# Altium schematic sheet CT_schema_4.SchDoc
size 284 x 147 mm
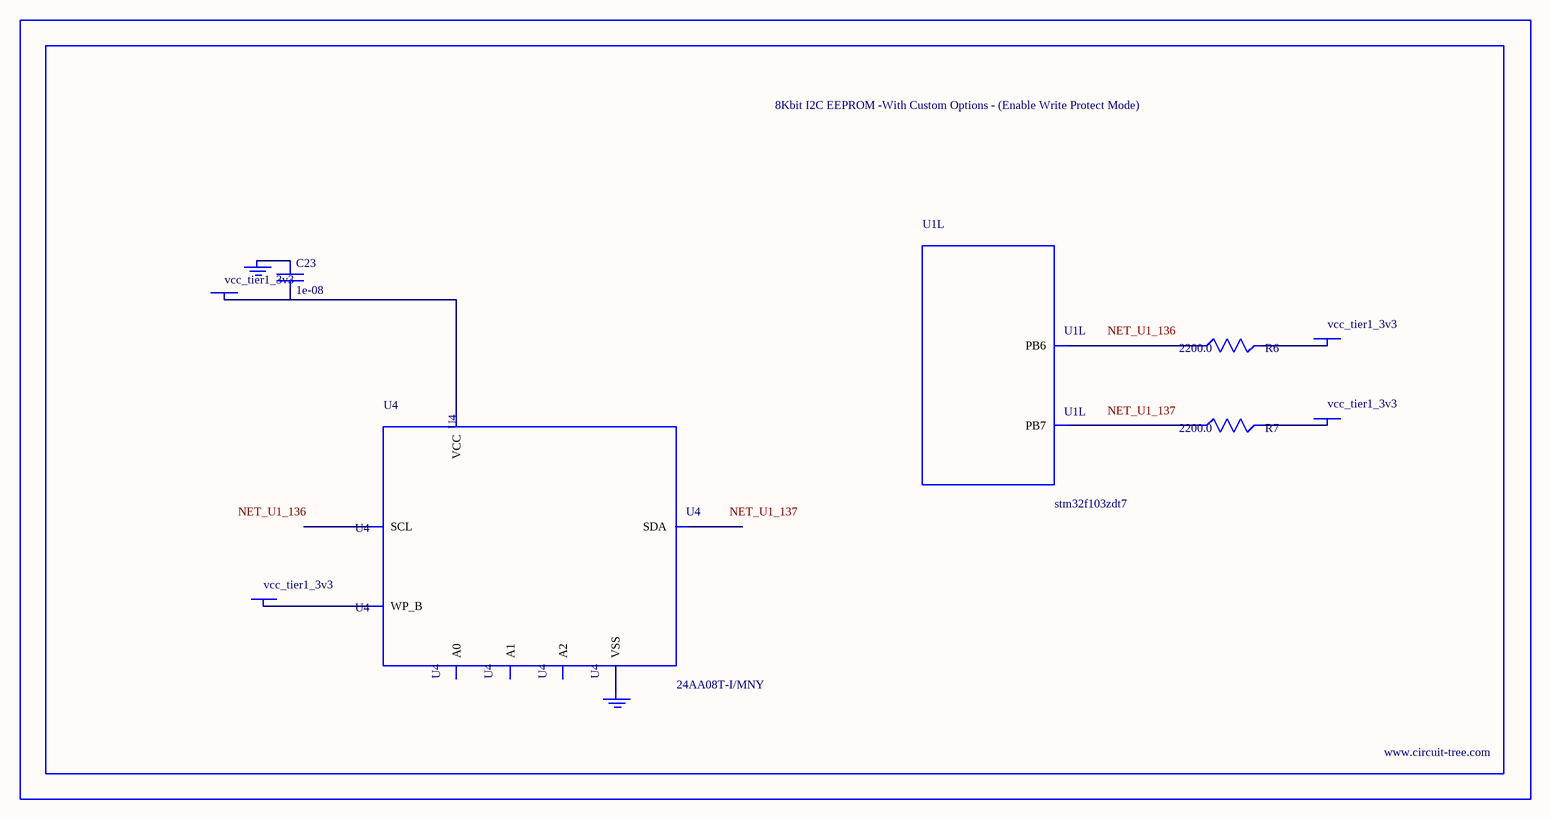
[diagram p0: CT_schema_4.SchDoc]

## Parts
BORDER3  (no value)
C23  1e-08  [C0402]
GND_INSTANCE_3_0  (no value)
GND_INSTANCE_3_1  (no value)
POWER_INSTANCE_3_0  vcc_tier1_3v3
POWER_INSTANCE_3_1  vcc_tier1_3v3
POWER_INSTANCE_3_2  vcc_tier1_3v3
POWER_INSTANCE_3_3  vcc_tier1_3v3
R6  2200.0  [R0603]
R7  2200.0  [R0603]
U1  stm32f103zdt7  [LQFP144]  (part L of 13)
U4  24AA08T-I/MNY  [TDFN-8/6MM]

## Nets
NetC23_1: C23.1 GND_INSTANCE_3_0.0(GND)
NetC23_2: C23.2 POWER_INSTANCE_3_1.0(PWR) U4.8(VCC)
NetGND_INSTANCE_3_1_0: GND_INSTANCE_3_1.0(GND) U4.4(VSS)
NetPOWER_INSTANCE_3_0_0: POWER_INSTANCE_3_0.0(PWR) U4.7(WP_B)
NetPOWER_INSTANCE_3_2_0: POWER_INSTANCE_3_2.0(PWR) R6.2
NetPOWER_INSTANCE_3_3_0: POWER_INSTANCE_3_3.0(PWR) R7.2
NetR6_1: R6.1 U1.136(PB6)
NetR7_1: R7.1 U1.137(PB7)

Not connected (* = marked no-connect by the designer): U4 1(A0) 2(A1) 3(A2) 5(SDA) 6(SCL)

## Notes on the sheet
- Labels drawn without touching a wire or pin: NET_U1_136, NET_U1_137

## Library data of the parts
BORDER3 = BORDER_PAGE3
C23 = C0402C103K3RAC
GND_INSTANCE_3_0 GND_INSTANCE_3_1 = GND
POWER_INSTANCE_3_0-POWER_INSTANCE_3_3 = PWR
R6 R7 = RC0603JR-072K2L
